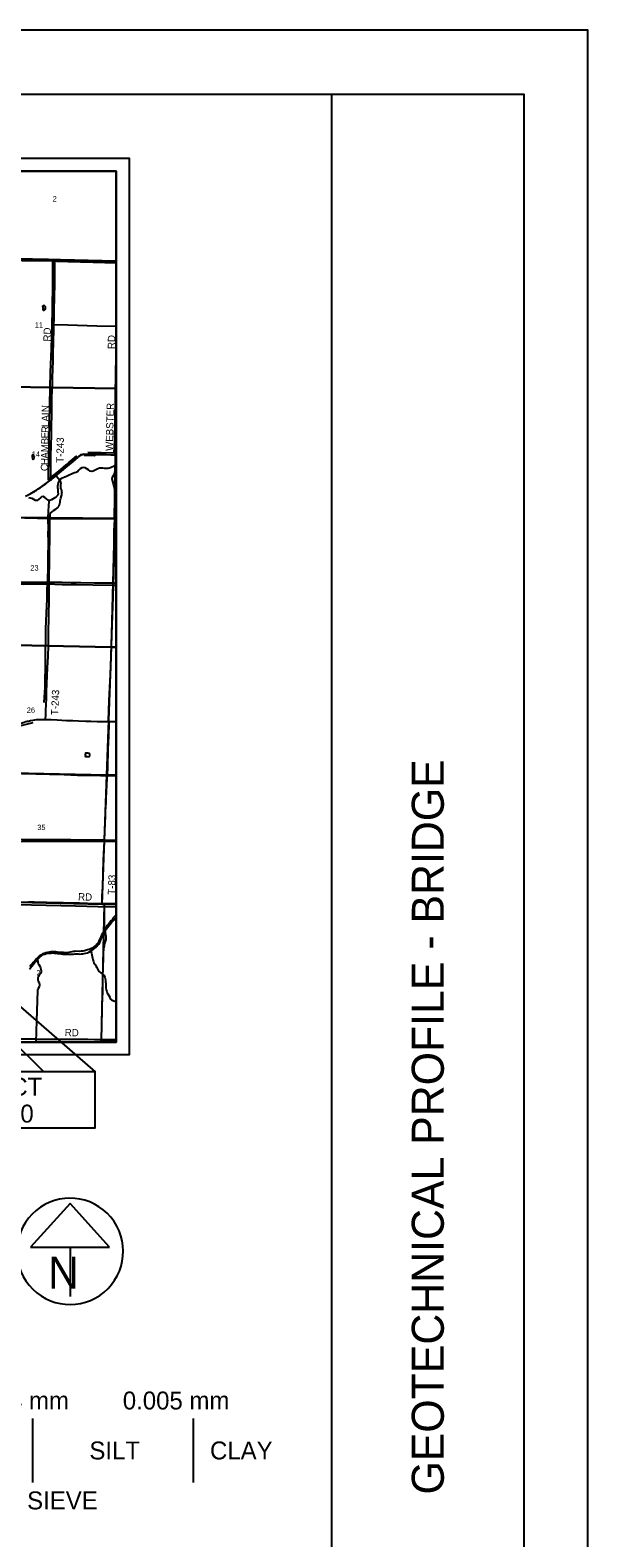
# Model space of a CAD drawing. Extents: x -59 to 43, y 0 to 22.
# Drawn here: x 29.64 to 34, y 10.23 to 22 of the extents above; entities that cross this region are included whole.
import ezdxf

# ---------------------------------------------------------------- set-up
doc = ezdxf.new("R2010")
doc.units = 0
for name, color, linetype in [('BR_P_Gen_Text', 7, 'Continuous'), ('Default', 7, 'Continuous'), ('GM_X_Interchange_Ramps', 7, 'Continuous'), ('GM_X_Major_River', 7, 'Continuous'), ('GM_X_Minor_Lake', 7, 'Continuous'), ('GM_X_Minor_River', 7, 'Continuous'), ('GM_X_Rail_Line', 7, 'Continuous'), ('GM_X_Section', 7, 'Continuous'), ('GM_X_Section_Text', 7, 'Continuous'), ('GM_X_State_Route', 7, 'Continuous'), ('GM_X_Township_Road', 7, 'Continuous'), ('GM_X_Township_Road_Text', 7, 'Continuous'), ('GM_X_US_Route', 7, 'Continuous'), ('SH_Border', 7, 'Continuous'), ('SH_Cut_Line', 7, 'Continuous'), ('SH_Data', 7, 'Continuous'), ('SH_Text', 7, 'Continuous')]:
    doc.layers.add(name, color=color, linetype=linetype)

msp = doc.modelspace()

# ---------------------------------------------------------------- linework, layer by layer
at = {"layer": 'BR_P_Gen_Text'}
for points in [[(26.836, 16.75), (30.153, 13.866), (29.75, 13.866)], [(30.153, 13.866), (28.358, 13.866), (28.15, 13.648), (28.358, 13.429), (30.153, 13.429)]]:
    msp.add_lwpolyline(points, close=True, dxfattribs=at)
at = {"layer": 'Default'}
for points in [[(30.317, 20.196), (30.317, 20.9), (29.334, 20.9), (29.334, 20.22)], [(30.317, 19.203), (30.317, 20.196), (29.334, 20.22), (29.309, 19.224), (29.309, 19.219)], [(30.317, 18.988), (30.317, 19.203), (29.309, 19.219), (29.297, 18.199), (30.302, 18.191)], [(30.317, 18.191), (30.317, 18.988), (30.302, 18.191)], [(30.317, 17.183), (30.317, 18.191), (30.302, 18.191), (30.278, 17.183)], [(30.317, 16.183), (30.317, 17.183), (30.278, 17.183), (30.241, 16.184)], [(30.317, 15.174), (30.317, 16.183), (30.241, 16.184), (30.203, 15.177), (30.223, 15.176)], [(30.317, 14.117), (30.317, 15.174), (30.223, 15.176), (30.198, 14.117)], [(29.194, 14.1), (30.198, 14.1), (30.198, 14.117), (29.194, 14.122)], [(30.198, 14.1), (30.317, 14.1), (30.317, 14.117), (30.198, 14.117)]]:
    msp.add_lwpolyline(points, close=True, dxfattribs=at)
at = {"layer": 'GM_X_Interchange_Ramps'}
for points in [[(29.308, 18.2), (29.799, 18.187), (30.3, 18.186), (30.317, 18.185), (30.317, 20.9), (29.337, 20.9)], [(29.632, 15.192), (29.676, 15.191), (29.772, 15.189), (29.856, 15.187), (29.903, 15.187), (30.03, 15.184), (30.092, 15.182), (30.206, 15.18), (30.226, 15.179), (30.317, 15.178), (30.317, 18.185), (30.3, 18.186), (29.799, 18.187), (29.308, 18.2)], [(25.144, 14.1), (30.317, 14.1), (30.317, 15.178), (30.226, 15.179), (30.206, 15.18), (30.092, 15.182), (30.03, 15.184), (29.903, 15.187), (29.856, 15.187), (29.772, 15.189), (29.676, 15.191), (29.632, 15.192)]]:
    msp.add_lwpolyline(points, dxfattribs=at)
at = {"layer": 'GM_X_Major_River'}
for points in [[(30.317, 18.604), (30.316, 18.604), (30.303, 18.601), (30.288, 18.591), (30.276, 18.585), (30.265, 18.581), (30.251, 18.578), (30.238, 18.577), (30.224, 18.578), (30.212, 18.581), (30.197, 18.58), (30.185, 18.579), (30.173, 18.574), (30.148, 18.562), (30.136, 18.557), (30.126, 18.554), (30.114, 18.556), (30.1, 18.566), (30.087, 18.575), (30.074, 18.582), (30.061, 18.586), (30.048, 18.582), (30.035, 18.574), (30.025, 18.564), (30.015, 18.551), (30.003, 18.547), (29.991, 18.543), (29.978, 18.538), (29.967, 18.533), (29.955, 18.528), (29.943, 18.523), (29.929, 18.516), (29.916, 18.509), (29.903, 18.504), (29.89, 18.499), (29.876, 18.491), (29.868, 18.48), (29.862, 18.466), (29.86, 18.453), (29.859, 18.441), (29.859, 18.43), (29.86, 18.416), (29.861, 18.405), (29.861, 18.392), (29.862, 18.383), (29.86, 18.369), (29.848, 18.356), (29.836, 18.348), (29.823, 18.341), (29.811, 18.334), (29.797, 18.329), (29.785, 18.331), (29.771, 18.341), (29.76, 18.352), (29.747, 18.358), (29.734, 18.356), (29.724, 18.349), (29.711, 18.337), (29.699, 18.328), (29.686, 18.327), (29.673, 18.336), (29.661, 18.343), (29.647, 18.347), (29.635, 18.348)], [(30.317, 15.092), (30.304, 15.08), (30.294, 15.069), (30.284, 15.055), (30.275, 15.045), (30.266, 15.033), (30.256, 15.02), (30.246, 15.009), (30.238, 14.996), (30.232, 14.986), (30.224, 14.975), (30.216, 14.962), (30.209, 14.948), (30.202, 14.934), (30.196, 14.922), (30.191, 14.911), (30.187, 14.9), (30.182, 14.888), (30.176, 14.875), (30.166, 14.864), (30.159, 14.857), (30.142, 14.842), (30.129, 14.834), (30.115, 14.827), (30.106, 14.823), (30.093, 14.819), (30.068, 14.812), (30.056, 14.809), (30.043, 14.808), (30.03, 14.807), (30.002, 14.808), (29.992, 14.807), (29.98, 14.806), (29.971, 14.804), (29.958, 14.801), (29.945, 14.798), (29.933, 14.797), (29.919, 14.797), (29.905, 14.798), (29.892, 14.798), (29.88, 14.799), (29.87, 14.8), (29.857, 14.802), (29.844, 14.804), (29.831, 14.804), (29.818, 14.804), (29.807, 14.803), (29.793, 14.802), (29.779, 14.799), (29.766, 14.796), (29.754, 14.792), (29.74, 14.788)], [(29.808, 14.794), (29.819, 14.795), (29.831, 14.794), (29.846, 14.793), (29.858, 14.792), (29.871, 14.791), (29.885, 14.789), (29.899, 14.787), (29.911, 14.786), (29.922, 14.785), (29.932, 14.786), (29.943, 14.786), (29.958, 14.786), (29.972, 14.786), (29.984, 14.787), (29.996, 14.788), (30.01, 14.788), (30.019, 14.788), (30.032, 14.787), (30.045, 14.788), (30.056, 14.789), (30.065, 14.79), (30.078, 14.793), (30.091, 14.797), (30.103, 14.802), (30.117, 14.81), (30.129, 14.819), (30.142, 14.828), (30.159, 14.841), (30.18, 14.864), (30.188, 14.877), (30.194, 14.89), (30.197, 14.899), (30.201, 14.909), (30.205, 14.921), (30.209, 14.934), (30.214, 14.946), (30.221, 14.958), (30.229, 14.971), (30.239, 14.982), (30.249, 14.995), (30.259, 15.007), (30.27, 15.019), (30.281, 15.032), (30.29, 15.043), (30.3, 15.054), (30.31, 15.067), (30.317, 15.074)], [(29.64, 14.67), (29.647, 14.68), (29.657, 14.693), (29.667, 14.705), (29.678, 14.717), (29.688, 14.729), (29.699, 14.741), (29.711, 14.754), (29.722, 14.766), (29.733, 14.774), (29.746, 14.782), (29.758, 14.786), (29.77, 14.791), (29.787, 14.793), (29.796, 14.794), (29.808, 14.794)], [(29.74, 14.788), (29.728, 14.779), (29.714, 14.769), (29.703, 14.758), (29.693, 14.749), (29.681, 14.735), (29.669, 14.722), (29.659, 14.711), (29.65, 14.699), (29.641, 14.686)]]:
    msp.add_lwpolyline(points, dxfattribs=at)
at = {"layer": 'GM_X_Minor_Lake'}
for p, q in [((29.744, 19.836), (29.744, 19.831)), ((29.66, 18.672), (29.661, 18.665)), ((30.108, 16.327), (30.111, 16.341))]:
    msp.add_line(p, q, dxfattribs=at)
for points in [[(29.744, 19.831), (29.745, 19.826), (29.744, 19.821), (29.746, 19.815), (29.75, 19.813), (29.755, 19.814), (29.762, 19.818), (29.763, 19.825), (29.763, 19.833), (29.763, 19.84), (29.76, 19.845), (29.756, 19.848), (29.749, 19.85), (29.742, 19.846), (29.744, 19.836)], [(29.661, 18.665), (29.662, 18.661), (29.662, 18.654), (29.667, 18.65), (29.674, 18.652), (29.676, 18.664), (29.673, 18.673), (29.673, 18.679), (29.668, 18.684), (29.663, 18.684), (29.66, 18.679), (29.66, 18.672)], [(30.111, 16.341), (30.111, 16.346), (30.108, 16.352), (30.104, 16.353), (30.094, 16.356), (30.076, 16.356), (30.075, 16.346), (30.076, 16.337), (30.075, 16.331), (30.079, 16.329), (30.093, 16.328), (30.108, 16.327)]]:
    msp.add_lwpolyline(points, dxfattribs=at)
at = {"layer": 'GM_X_Minor_River'}
for points in [[(30.317, 20.18), (30.136, 20.187), (29.939, 20.192), (29.85, 20.195), (29.82, 20.196), (29.581, 20.2), (29.444, 20.203), (29.343, 20.206), (29.323, 20.206), (29.228, 20.206), (29.053, 20.209), (28.928, 20.208), (28.822, 20.209), (28.692, 20.21), (28.585, 20.212), (28.445, 20.215), (28.331, 20.217)], [(29.82, 20.196), (29.82, 20.035), (29.817, 19.811), (29.814, 19.699), (29.808, 19.512), (29.802, 19.33), (29.798, 19.211), (29.792, 18.936), (29.79, 18.796), (29.787, 18.642), (29.785, 18.533), (29.784, 18.491), (29.831, 18.527), (29.883, 18.571), (29.926, 18.605), (29.95, 18.626), (29.976, 18.648), (30.01, 18.676)], [(30.317, 19.686), (30.164, 19.69), (29.938, 19.696), (29.814, 19.699)], [(30.317, 19.597), (30.315, 19.503), (30.312, 19.342), (30.308, 19.127), (30.307, 18.954), (30.303, 18.798), (30.298, 18.698), (30.198, 18.7), (30.148, 18.701), (30.096, 18.703)], [(30.148, 18.701), (30.146, 18.676), (30.065, 18.679)], [(30.312, 18.603), (30.311, 18.593), (30.308, 18.57), (30.305, 18.554), (30.3, 18.537), (30.292, 18.521), (30.286, 18.508), (30.283, 18.5), (30.284, 18.487), (30.289, 18.469), (30.295, 18.449), (30.3, 18.428), (30.302, 18.416), (30.303, 18.401), (30.302, 18.35), (30.303, 18.263), (30.302, 18.18), (30.299, 18.091), (30.299, 17.974), (30.298, 17.859), (30.296, 17.758), (30.294, 17.666), (30.29, 17.576), (30.287, 17.501)], [(29.791, 18.33), (29.787, 18.276), (29.786, 18.254), (29.784, 18.23), (29.783, 18.205), (29.783, 18.166), (29.784, 18.12), (29.783, 18.062), (29.785, 18.017), (29.784, 17.971), (29.783, 17.913), (29.782, 17.857), (29.782, 17.79), (29.779, 17.727), (29.779, 17.697), (29.777, 17.693), (29.778, 17.676), (29.775, 17.627), (29.775, 17.551), (29.772, 17.508)], [(29.301, 17.674), (29.304, 17.676), (29.305, 17.677), (29.31, 17.678), (29.331, 17.678), (29.386, 17.678), (29.515, 17.677), (29.594, 17.675), (29.691, 17.676), (29.778, 17.676), (29.894, 17.673), (30.003, 17.671), (30.135, 17.67), (30.294, 17.666), (30.317, 17.666)], [(29.772, 17.508), (29.765, 17.325), (29.762, 17.079), (29.758, 16.867), (29.752, 16.75)], [(30.287, 17.501), (30.278, 17.209), (30.271, 17.022), (30.259, 16.767), (30.253, 16.607)], [(29.261, 16.411), (29.264, 16.404), (29.289, 16.419), (29.286, 16.423), (29.345, 16.459), (29.374, 16.479), (29.406, 16.497), (29.438, 16.515), (29.467, 16.534), (29.501, 16.55), (29.524, 16.559), (29.55, 16.567), (29.585, 16.574), (29.617, 16.581), (29.668, 16.595)], [(30.317, 16.178), (30.257, 16.178), (30.195, 16.177), (30.092, 16.181), (30.013, 16.182), (29.91, 16.185), (29.796, 16.189), (29.688, 16.191), (29.58, 16.194), (29.471, 16.198), (29.364, 16.199), (29.3, 16.199)], [(30.317, 15.663), (30.181, 15.665), (29.843, 15.665), (29.534, 15.664), (29.278, 15.664)], [(27.509, 15.215), (27.775, 15.209), (27.917, 15.204), (28.096, 15.202), (28.308, 15.199), (28.56, 15.195), (28.778, 15.19), (29.078, 15.186), (29.206, 15.183), (29.425, 15.177), (29.77, 15.168), (29.998, 15.163), (30.175, 15.159), (30.317, 15.156)], [(29.702, 14.744), (29.704, 14.726), (29.708, 14.713), (29.713, 14.704), (29.719, 14.691), (29.724, 14.678), (29.728, 14.668), (29.731, 14.656), (29.73, 14.646), (29.725, 14.636), (29.716, 14.622), (29.707, 14.609), (29.704, 14.598), (29.704, 14.585), (29.708, 14.575), (29.714, 14.562), (29.717, 14.552), (29.718, 14.542), (29.716, 14.532), (29.706, 14.518), (29.703, 14.506), (29.703, 14.492)], [(30.119, 14.812), (30.123, 14.794), (30.125, 14.781), (30.129, 14.768), (30.131, 14.754), (30.134, 14.744), (30.139, 14.729), (30.143, 14.718), (30.151, 14.705), (30.157, 14.695), (30.165, 14.682), (30.17, 14.672), (30.176, 14.661), (30.183, 14.651), (30.196, 14.639), (30.209, 14.629), (30.222, 14.619), (30.227, 14.607), (30.23, 14.596), (30.233, 14.581), (30.234, 14.571), (30.235, 14.558), (30.235, 14.545), (30.236, 14.534), (30.236, 14.523), (30.239, 14.508), (30.243, 14.495), (30.246, 14.485), (30.251, 14.476), (30.259, 14.463), (30.266, 14.45), (30.269, 14.437), (30.281, 14.429), (30.291, 14.425), (30.306, 14.419), (30.317, 14.411)], [(29.703, 14.502), (29.695, 14.265), (29.688, 14.1)]]:
    msp.add_lwpolyline(points, dxfattribs=at)
at = {"layer": 'GM_X_Rail_Line'}
msp.add_lwpolyline([(29.609, 18.362), (29.678, 18.399), (29.736, 18.437), (29.807, 18.489), (29.858, 18.533), (29.956, 18.615), (30.022, 18.67), (30.043, 18.687), (30.065, 18.693), (30.311, 18.685), (30.317, 18.686)], dxfattribs=at)
at = {"layer": 'GM_X_Section'}
for points in [[(29.297, 18.199), (30.302, 18.191), (30.278, 17.183), (29.282, 17.204)], [(29.282, 17.204), (30.278, 17.183), (30.241, 16.184), (29.261, 16.205)], [(30.241, 16.184), (30.203, 15.177), (29.223, 15.2), (29.207, 15.201), (29.261, 16.205)], [(29.223, 15.2), (30.203, 15.177), (30.223, 15.176), (30.198, 14.117), (29.194, 14.122)]]:
    msp.add_lwpolyline(points, close=True, dxfattribs=at)
at = {"layer": 'GM_X_State_Route'}
for points in [[(29.847, 18.522), (29.858, 18.531), (29.89, 18.558), (29.924, 18.586), (29.948, 18.606), (29.978, 18.631), (29.996, 18.646), (30.02, 18.666), (30.029, 18.674), (30.036, 18.679), (30.04, 18.681), (30.043, 18.683), (30.046, 18.685), (30.049, 18.686), (30.051, 18.687), (30.054, 18.688), (30.057, 18.688), (30.06, 18.689), (30.063, 18.689), (30.067, 18.69), (30.074, 18.69), (30.086, 18.69), (30.151, 18.688), (30.21, 18.687), (30.239, 18.686), (30.275, 18.684), (30.293, 18.684), (30.304, 18.683), (30.312, 18.684), (30.313, 18.684), (30.317, 18.684)], [(29.644, 18.381), (29.657, 18.388), (29.683, 18.402), (29.695, 18.409), (29.708, 18.418), (29.723, 18.427), (29.737, 18.437), (29.763, 18.456), (29.789, 18.476), (29.804, 18.487), (29.808, 18.49)], [(29.808, 18.49), (29.822, 18.501), (29.838, 18.515), (29.847, 18.522)]]:
    msp.add_lwpolyline(points, dxfattribs=at)
at = {"layer": 'GM_X_Township_Road'}
for p, q in [((30.226, 15.179), (30.206, 15.18)), ((30.226, 15.179), (30.317, 15.177)), ((30.2, 14.1), (30.201, 14.12))]:
    msp.add_line(p, q, dxfattribs=at)
for points in [[(29.336, 20.222), (29.385, 20.221), (29.504, 20.218), (29.653, 20.214), (29.705, 20.213), (29.789, 20.211), (29.838, 20.209)], [(29.808, 18.49), (29.806, 18.497), (29.805, 18.5), (29.805, 18.503), (29.804, 18.506), (29.805, 18.518), (29.806, 18.556), (29.806, 18.602), (29.807, 18.667), (29.809, 18.767), (29.81, 18.829), (29.811, 18.919), (29.813, 18.99), (29.814, 19.059), (29.815, 19.096), (29.815, 19.127), (29.817, 19.189), (29.819, 19.245), (29.82, 19.295), (29.821, 19.344), (29.823, 19.425), (29.824, 19.478), (29.826, 19.565), (29.829, 19.664), (29.832, 19.782), (29.833, 19.822), (29.834, 19.906), (29.836, 20.031), (29.837, 20.096), (29.838, 20.18), (29.838, 20.204), (29.838, 20.209)], [(29.838, 20.209), (29.867, 20.209), (29.954, 20.206), (30.01, 20.205), (30.075, 20.203), (30.215, 20.2), (30.317, 20.197)], [(30.312, 18.684), (30.312, 18.69), (30.312, 18.73), (30.313, 18.752), (30.314, 18.789), (30.316, 18.827), (30.317, 18.856)], [(29.799, 18.186), (29.799, 18.194), (29.8, 18.207), (29.8, 18.213), (29.801, 18.219), (29.802, 18.222), (29.802, 18.225), (29.804, 18.227), (29.805, 18.23), (29.807, 18.233), (29.809, 18.235), (29.811, 18.237), (29.813, 18.239), (29.815, 18.241), (29.818, 18.243), (29.828, 18.25), (29.848, 18.264), (29.855, 18.27), (29.861, 18.274), (29.863, 18.276), (29.865, 18.278), (29.867, 18.281), (29.869, 18.283), (29.87, 18.286), (29.871, 18.289), (29.872, 18.292), (29.873, 18.295), (29.875, 18.304), (29.878, 18.316), (29.88, 18.325), (29.885, 18.347), (29.889, 18.365), (29.891, 18.371), (29.892, 18.377), (29.893, 18.383), (29.893, 18.386), (29.894, 18.389), (29.893, 18.392), (29.893, 18.395), (29.892, 18.399), (29.892, 18.402), (29.891, 18.405), (29.888, 18.411), (29.885, 18.419), (29.884, 18.422), (29.884, 18.425), (29.883, 18.428), (29.883, 18.431), (29.883, 18.434), (29.883, 18.437), (29.883, 18.44), (29.883, 18.443), (29.885, 18.455), (29.886, 18.459), (29.886, 18.462), (29.886, 18.465), (29.885, 18.468), (29.884, 18.471), (29.883, 18.474), (29.881, 18.477), (29.875, 18.484), (29.864, 18.499), (29.851, 18.516), (29.847, 18.522)], [(29.847, 18.522), (29.838, 18.515), (29.822, 18.501), (29.808, 18.49)], [(29.794, 17.69), (29.794, 17.694), (29.794, 17.766), (29.795, 17.809), (29.796, 17.93), (29.798, 18.027), (29.798, 18.033), (29.798, 18.036), (29.798, 18.042), (29.799, 18.098), (29.799, 18.12), (29.799, 18.135), (29.799, 18.163), (29.799, 18.186)], [(29.29, 17.444), (29.29, 17.46), (29.29, 17.509), (29.292, 17.606), (29.293, 17.633), (29.293, 17.662), (29.293, 17.674), (29.293, 17.68), (29.293, 17.683), (29.295, 17.686), (29.296, 17.688), (29.298, 17.69), (29.301, 17.692), (29.303, 17.693), (29.306, 17.693), (29.315, 17.693), (29.376, 17.692), (29.451, 17.692), (29.547, 17.691), (29.634, 17.69), (29.724, 17.69), (29.759, 17.69), (29.786, 17.69), (29.794, 17.69)], [(29.764, 16.619), (29.765, 16.628), (29.766, 16.646), (29.767, 16.684), (29.769, 16.74), (29.771, 16.777), (29.773, 16.836), (29.78, 17.022), (29.784, 17.109), (29.787, 17.196), (29.787, 17.231), (29.789, 17.327), (29.79, 17.389), (29.791, 17.433), (29.793, 17.551), (29.793, 17.61), (29.794, 17.679), (29.794, 17.69)], [(29.794, 17.69), (29.821, 17.69), (29.858, 17.69), (29.895, 17.689), (29.964, 17.688), (30.041, 17.687), (30.144, 17.686), (30.228, 17.685), (30.317, 17.684)], [(30.226, 15.678), (30.226, 15.681), (30.226, 15.695), (30.227, 15.72), (30.228, 15.762), (30.229, 15.788), (30.23, 15.812), (30.232, 15.859), (30.234, 15.897), (30.236, 15.941), (30.237, 15.966), (30.239, 16.003), (30.241, 16.05), (30.244, 16.11), (30.245, 16.153), (30.248, 16.186), (30.249, 16.212), (30.25, 16.225), (30.25, 16.243), (30.25, 16.251), (30.251, 16.28), (30.252, 16.289), (30.253, 16.338), (30.254, 16.38), (30.256, 16.439), (30.258, 16.486), (30.259, 16.516), (30.261, 16.558), (30.262, 16.578), (30.262, 16.598), (30.262, 16.602)], [(29.243, 15.684), (29.247, 15.683), (29.255, 15.683), (29.267, 15.683), (29.307, 15.683), (29.428, 15.683), (29.497, 15.683), (29.536, 15.683), (29.581, 15.682), (29.654, 15.681), (29.717, 15.681), (29.754, 15.681), (29.843, 15.68), (29.88, 15.68), (29.937, 15.68), (29.963, 15.68), (30.001, 15.679), (30.042, 15.679), (30.095, 15.679), (30.153, 15.679), (30.183, 15.679), (30.219, 15.679), (30.226, 15.678)], [(30.206, 15.18), (30.206, 15.203), (30.208, 15.245), (30.209, 15.273), (30.211, 15.316), (30.214, 15.41), (30.215, 15.446), (30.216, 15.487), (30.218, 15.521), (30.22, 15.571), (30.222, 15.619), (30.224, 15.651), (30.225, 15.671), (30.226, 15.678)], [(30.226, 15.678), (30.301, 15.677), (30.317, 15.677)], [(29.226, 15.2), (29.319, 15.198), (29.458, 15.196), (29.505, 15.195), (29.57, 15.193), (29.632, 15.192), (29.676, 15.191), (29.772, 15.189), (29.856, 15.187), (29.903, 15.186), (30.03, 15.184), (30.092, 15.182), (30.206, 15.18)], [(30.201, 14.12), (30.202, 14.138), (30.203, 14.216), (30.205, 14.266), (30.207, 14.343), (30.208, 14.402), (30.209, 14.443), (30.211, 14.493), (30.212, 14.555), (30.213, 14.586), (30.213, 14.617), (30.214, 14.67), (30.215, 14.701), (30.216, 14.738), (30.218, 14.788), (30.218, 14.807), (30.219, 14.819), (30.22, 14.831), (30.222, 14.841), (30.224, 14.853), (30.228, 14.868), (30.235, 14.892), (30.237, 14.901), (30.238, 14.907), (30.238, 14.913), (30.237, 14.923), (30.236, 14.938), (30.23, 14.978), (30.225, 15.012), (30.224, 15.024), (30.224, 15.037), (30.224, 15.052), (30.225, 15.105), (30.226, 15.142), (30.226, 15.179)], [(29.202, 14.123), (29.242, 14.123), (29.267, 14.123), (29.302, 14.124), (29.326, 14.124), (29.342, 14.124), (29.407, 14.124), (29.463, 14.124), (29.532, 14.124), (29.566, 14.124), (29.643, 14.124), (29.687, 14.124), (29.724, 14.123), (29.836, 14.124), (29.898, 14.123), (29.933, 14.123), (29.976, 14.122), (30.038, 14.122), (30.094, 14.121), (30.147, 14.12), (30.201, 14.12)], [(30.201, 14.12), (30.212, 14.119), (30.243, 14.119), (30.275, 14.119), (30.317, 14.117)]]:
    msp.add_lwpolyline(points, dxfattribs=at)
at = {"layer": 'GM_X_US_Route'}
for points in [[(29.552, 16.582), (29.558, 16.584), (29.583, 16.593), (29.598, 16.598), (29.61, 16.602), (29.62, 16.604), (29.631, 16.606), (29.648, 16.609), (29.668, 16.613), (29.681, 16.615), (29.695, 16.617), (29.711, 16.618), (29.724, 16.618), (29.738, 16.619), (29.753, 16.619), (29.764, 16.619), (29.775, 16.619), (29.79, 16.618)], [(29.79, 16.618), (29.808, 16.618), (29.855, 16.615), (29.929, 16.611), (29.979, 16.609), (30.022, 16.607), (30.078, 16.605), (30.119, 16.604), (30.169, 16.603), (30.245, 16.602), (30.262, 16.602), (30.28, 16.602), (30.306, 16.602), (30.317, 16.601)]]:
    msp.add_lwpolyline(points, dxfattribs=at)
at = {"layer": 'SH_Border'}
msp.add_line((32, 0.5), (32, 21.5), dxfattribs=at)
msp.add_lwpolyline([(1.5, 21.5), (33.5, 21.5), (33.5, 0.5), (1.5, 0.5)], close=True, dxfattribs=at)
at = {"layer": 'SH_Cut_Line'}
msp.add_lwpolyline([(0, 0), (34, 0), (34, 22), (0, 22)], close=True, dxfattribs=at)
at = {"layer": 'SH_Data'}
for p, q in [((29.956, 12.84), (29.648, 12.499)), ((30.264, 12.499), (29.956, 12.84)), ((29.648, 12.499), (30.264, 12.499)), ((29.956, 12.499), (29.956, 12.112)), ((29.665, 10.661), (29.665, 11.161)), ((30.919, 10.661), (30.919, 11.161))]:
    msp.add_line(p, q, dxfattribs=at)
for points in [[(23.417, 21), (30.417, 21), (30.417, 14), (23.417, 14)], [(23.517, 20.9), (30.317, 20.9), (30.317, 14.1), (23.517, 14.1)]]:
    msp.add_lwpolyline(points, close=True, dxfattribs=at)
msp.add_arc((29.956, 12.466), 0.415, 129.7798, 129.7633, dxfattribs=at)

# ---------------------------------------------------------------- texts
at = {"layer": 'GM_X_Section_Text'}
for s, p in [('2', (29.82, 20.662)), ('11', (29.681, 19.678)), ('14', (29.657, 18.669)), ('23', (29.646, 17.781)), ('26', (29.618, 16.67)), ('35', (29.7, 15.755)), ('2', (29.694, 14.62))]:
    msp.add_text(s, height=0.0419, rotation=0, dxfattribs=at).set_placement(p)
at = {"layer": 'GM_X_Township_Road_Text'}
for s, rotation, p in [('RD', 88.5175, (29.804, 19.568)), ('RD', 89.5063, (30.307, 19.51)), ('WEBSTER', 88.542, (30.29, 18.714)), ('I', 89.1179, (29.791, 18.994)), ('A', 89.1403, (29.79, 18.944)), ('N', 88.4662, (29.791, 19.017)), ('E', 89.1416, (29.788, 18.812)), ('R', 89.1413, (29.789, 18.855)), ('L', 89.1416, (29.79, 18.901)), ('M', 89.1429, (29.787, 18.704)), ('B', 89.1413, (29.787, 18.766)), ('T-243', 89.1729, (29.905, 18.622)), ('C', 89.1413, (29.784, 18.557)), ('H', 89.1441, (29.785, 18.604)), ('A', 89.1403, (29.786, 18.654)), ('T-243', 87.7531, (29.864, 16.651)), ('T-83', 87.8787, (30.307, 15.249)), ('RD', 358.5248, (30.018, 15.206)), ('RD', 359.0265, (29.914, 14.146))]:
    msp.add_text(s, height=0.0568, rotation=rotation, dxfattribs=at).set_placement(p)
at = {"layer": 'SH_Data'}
msp.add_text('GEOTECHNICAL PROFILE - BRIDGE', height=0.25, rotation=90, dxfattribs=at).set_placement((32.875, 10.567))
msp.add_text('N', height=0.25, dxfattribs=at).set_placement((29.784, 12.175))
at = {"layer": 'SH_Text'}
for s, p in [('END PROJECT', (28.418, 13.681)), ('STA. 55+85.00', (28.418, 13.471)), ('0.074 mm', (29.115, 11.231)), ('0.005 mm', (30.368, 11.231)), ('SILT', (30.107, 10.841)), ('CLAY', (31.049, 10.841)), ('No. 200 SIEVE', (28.913, 10.451))]:
    msp.add_text(s, height=0.14, dxfattribs=at).set_placement(p)

doc.saveas('drawing.dxf')
